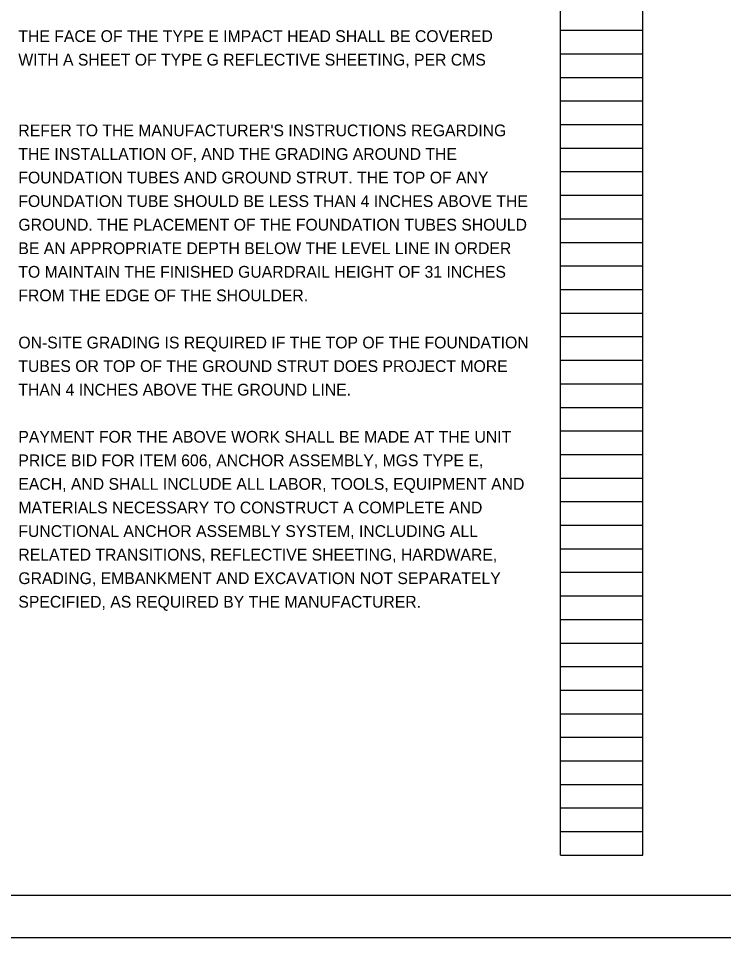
# Model space of a CAD drawing. Extents: x -5.3 to 69.2, y -33.8 to 22.
# Drawn here: x 17.24 to 25.62, y 0 to 10.92 of the extents above; entities that cross this region are included whole.
import ezdxf

# ---------------------------------------------------------------- set-up
doc = ezdxf.new("R2010")
doc.units = 0
for name, color, linetype in [('SH_Border', 7, 'Continuous'), ('SH_Cut_Line', 7, 'Continuous'), ('SH_Data', 7, 'Continuous'), ('SH_Text', 7, 'Continuous')]:
    doc.layers.add(name, color=color, linetype=linetype)

msp = doc.modelspace()

# ---------------------------------------------------------------- linework, layer by layer
at = {"layer": 'SH_Border'}
msp.add_lwpolyline([(1.5, 21.5), (33.5, 21.5), (33.5, 0.5), (1.5, 0.5)], close=True, dxfattribs=at)
at = {"layer": 'SH_Cut_Line'}
msp.add_lwpolyline([(0, 0), (34, 0), (34, 22), (0, 22)], close=True, dxfattribs=at)
at = {"layer": 'SH_Data'}
for p, q in [((23.68, 0.98), (23.68, 21.14)), ((24.66, 0.98), (24.66, 21.14)), ((23.68, 10.78), (24.66, 10.78)), ((23.68, 10.5), (24.66, 10.5)), ((23.68, 10.22), (24.66, 10.22)), ((23.68, 9.94), (24.66, 9.94)), ((23.68, 9.66), (24.66, 9.66)), ((23.68, 9.38), (24.66, 9.38)), ((23.68, 9.1), (24.66, 9.1)), ((23.68, 8.82), (24.66, 8.82)), ((23.68, 8.54), (24.66, 8.54)), ((23.68, 8.26), (24.66, 8.26)), ((23.68, 7.98), (24.66, 7.98)), ((23.68, 7.7), (24.66, 7.7)), ((23.68, 7.42), (24.66, 7.42)), ((23.68, 7.14), (24.66, 7.14)), ((23.68, 6.86), (24.66, 6.86)), ((23.68, 6.58), (24.66, 6.58)), ((23.68, 6.3), (24.66, 6.3)), ((23.68, 6.02), (24.66, 6.02)), ((23.68, 5.74), (24.66, 5.74)), ((23.68, 5.46), (24.66, 5.46)), ((23.68, 5.18), (24.66, 5.18)), ((23.68, 4.9), (24.66, 4.9)), ((23.68, 4.62), (24.66, 4.62)), ((23.68, 4.34), (24.66, 4.34)), ((23.68, 4.06), (24.66, 4.06)), ((23.68, 3.78), (24.66, 3.78)), ((23.68, 3.5), (24.66, 3.5)), ((23.68, 3.22), (24.66, 3.22)), ((23.68, 2.94), (24.66, 2.94)), ((23.68, 2.66), (24.66, 2.66)), ((23.68, 2.38), (24.66, 2.38)), ((23.68, 2.1), (24.66, 2.1)), ((23.68, 1.82), (24.66, 1.82)), ((23.68, 1.54), (24.66, 1.54)), ((23.68, 1.26), (24.66, 1.26)), ((23.68, 0.98), (24.66, 0.98))]:
    msp.add_line(p, q, dxfattribs=at)

# ---------------------------------------------------------------- texts
at = {"layer": 'SH_Text'}
for s, p in [('THE FACE OF THE TYPE E IMPACT HEAD SHALL BE COVERED', (17.24, 10.64)), ('WITH A SHEET OF TYPE G REFLECTIVE SHEETING, PER CMS', (17.24, 10.36)), ("REFER TO THE MANUFACTURER'S INSTRUCTIONS REGARDING", (17.24, 9.52)), ('THE INSTALLATION OF, AND THE GRADING AROUND THE', (17.24, 9.24)), ('FOUNDATION TUBES AND GROUND STRUT. THE TOP OF ANY', (17.24, 8.96)), ('FOUNDATION TUBE SHOULD BE LESS THAN 4 INCHES ABOVE THE', (17.24, 8.68)), ('GROUND. THE PLACEMENT OF THE FOUNDATION TUBES SHOULD', (17.24, 8.4)), ('BE AN APPROPRIATE DEPTH BELOW THE LEVEL LINE IN ORDER', (17.24, 8.12)), ('TO MAINTAIN THE FINISHED GUARDRAIL HEIGHT OF 31 INCHES', (17.24, 7.84)), ('FROM THE EDGE OF THE SHOULDER.', (17.24, 7.56)), ('ON-SITE GRADING IS REQUIRED IF THE TOP OF THE FOUNDATION', (17.24, 7)), ('TUBES OR TOP OF THE GROUND STRUT DOES PROJECT MORE', (17.24, 6.72)), ('THAN 4 INCHES ABOVE THE GROUND LINE.', (17.24, 6.44)), ('PAYMENT FOR THE ABOVE WORK SHALL BE MADE AT THE UNIT', (17.24, 5.88)), ('PRICE BID FOR ITEM 606, ANCHOR ASSEMBLY, MGS TYPE E,', (17.24, 5.6)), ('EACH, AND SHALL INCLUDE ALL LABOR, TOOLS, EQUIPMENT AND', (17.24, 5.32)), ('MATERIALS NECESSARY TO CONSTRUCT A COMPLETE AND', (17.24, 5.04)), ('FUNCTIONAL ANCHOR ASSEMBLY SYSTEM, INCLUDING ALL', (17.24, 4.76)), ('RELATED TRANSITIONS, REFLECTIVE SHEETING, HARDWARE,', (17.24, 4.48)), ('GRADING, EMBANKMENT AND EXCAVATION NOT SEPARATELY', (17.24, 4.2)), ('SPECIFIED, AS REQUIRED BY THE MANUFACTURER.', (17.24, 3.92))]:
    msp.add_text(s, height=0.14, dxfattribs=at).set_placement(p)

doc.saveas('drawing.dxf')
